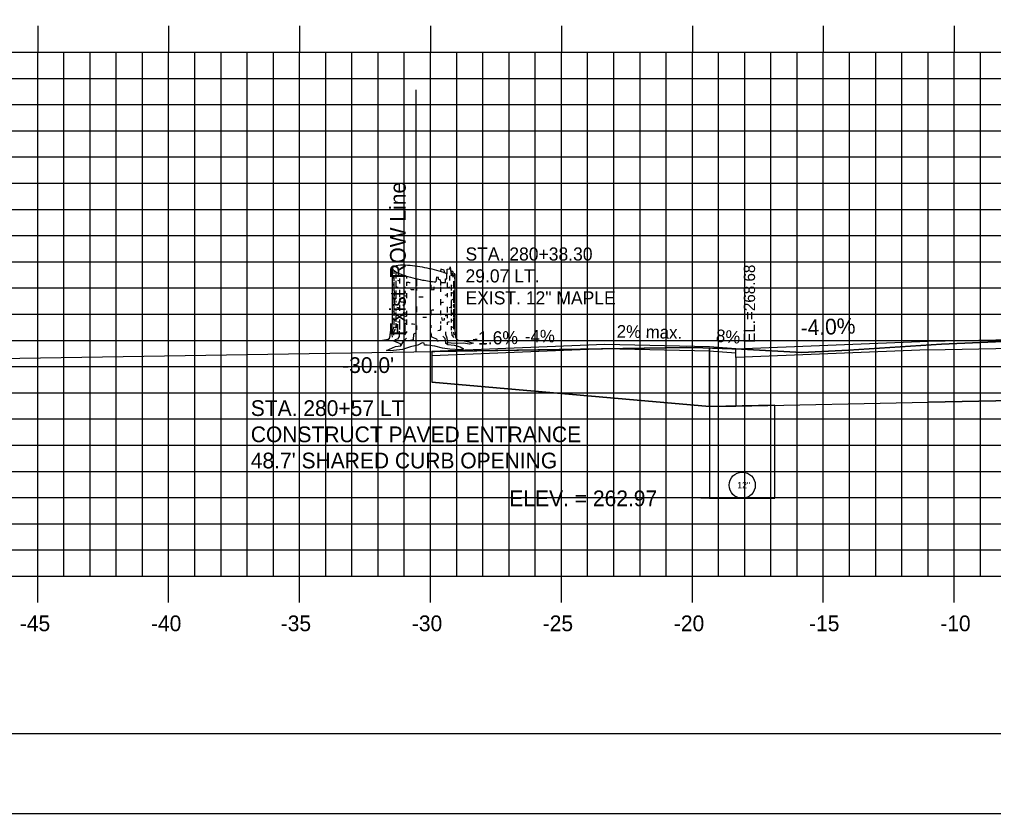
# Model space of a CAD drawing. Extents: x 855344 to 855514, y 366268 to 366378.
# Drawn here: x 855381.41 to 855418.61, y 366268.18 to 366298.48 of the extents above; entities that cross this region are included whole.
import ezdxf

# ---------------------------------------------------------------- set-up
doc = ezdxf.new("R2010")
doc.units = 0
for name, color, linetype in [('ANNOTATION', 7, 'Continuous'), ('BORDER', 7, 'Continuous'), ('D_Roadway_Drive_Gravel_LT', 7, 'Continuous'), ('D_Roadway_Drive_SubGrade', 7, 'Continuous'), ('D_Roadway_Edge_Shoulder', 7, 'Continuous'), ('D_Roadway_SubGrade', 7, 'Continuous'), ('D_Text_Monospaced', 7, 'Continuous'), ('D_Text_Standard', 7, 'Continuous'), ('E_ROW_Line', 7, 'Continuous'), ('H_V ANNOTATION', 7, 'Continuous'), ('JUNK COM EXC', 7, 'Continuous'), ('junk strct exc', 7, 'Continuous'), ('MAJOR', 7, 'Continuous'), ('MINOR', 7, 'Continuous'), ('PDRAIN', 7, 'Continuous'), ('PLOT BOUNDARY', 7, 'Continuous'), ('S_Roadway_Centerline', 7, 'Continuous'), ('S_Trees_Decid_Pay', 7, 'Continuous')]:
    doc.layers.add(name, color=color, linetype=linetype)

msp = doc.modelspace()

# ---------------------------------------------------------------- linework, layer by layer
at = {"layer": 'BORDER'}
msp.add_line((855352.11, 366271.236), (855512.11, 366271.236), dxfattribs=at)
at = {"layer": 'D_Roadway_Drive_Gravel_LT'}
for p, q in [((855403.764, 366286.075), (855397.155, 366285.81)), ((855407.764, 366285.995), (855403.764, 366286.075)), ((855408.764, 366285.915), (855407.764, 366285.995)), ((855403.771, 366285.908), (855397.155, 366285.643)), ((855407.761, 366285.828), (855403.761, 366285.908)), ((855408.764, 366285.747), (855407.751, 366285.828)), ((855408.764, 366285.581), (855408.764, 366285.915))]:
    msp.add_line(p, q, dxfattribs=at)
at = {"layer": 'D_Roadway_Drive_SubGrade'}
for p, q in [((855397.155, 366285.81), (855397.155, 366284.644)), ((855407.764, 366283.708), (855397.155, 366284.644)), ((855408.764, 366283.728), (855407.764, 366283.708))]:
    msp.add_line(p, q, dxfattribs=at)
at = {"layer": 'D_Roadway_Edge_Shoulder'}
msp.add_lwpolyline([(855408.764, 366285.915), (855416.11, 366286.208), (855427.11, 366286.428), (855438.11, 366286.208), (855442.107, 366286.048)], dxfattribs=at)
at = {"layer": 'D_Roadway_SubGrade'}
for points in [[(855416.11, 366283.875), (855416.11, 366285.875), (855427.11, 366286.095), (855438.11, 366285.875), (855438.11, 366283.875), (855427.11, 366284.095)], [(855416.11, 366285.875), (855408.764, 366285.581), (855408.764, 366283.728), (855416.11, 366283.875)]]:
    msp.add_lwpolyline(points, close=True, dxfattribs=at)
at = {"layer": 'D_Text_Standard'}
msp.add_lwpolyline([(855407.764, 366280.207), (855408.116, 366280.207), (855407.436, 366280.207)], dxfattribs=at)
at = {"layer": 'E_ROW_Line'}
msp.add_line((855396.563, 366285.801), (855396.563, 366295.801), dxfattribs=at)
at = {"layer": 'JUNK COM EXC'}
msp.add_lwpolyline([(855455.456, 366286.494), (855448.857, 366286.219), (855446.795, 366286.149), (855444.06, 366286.162), (855443.249, 366286.287), (855441.994, 366286.262), (855438.341, 366286.386), (855434.651, 366286.447), (855427.383, 366286.558), (855424.003, 366286.406), (855416.618, 366286.097), (855413.068, 366285.862), (855411.293, 366285.775), (855408.987, 366285.898), (855407.764, 366285.942), (855407.764, 366283.708), (855408.764, 366283.728), (855416.11, 366283.875), (855427.11, 366284.095), (855438.11, 366283.875), (855442.11, 366283.795), (855443.107, 366283.775), (855447.496, 366283.687), (855455.456, 366285.327)], close=True, dxfattribs=at)
msp.add_lwpolyline([(855407.764, 366285.942), (855407.512, 366285.951), (855406.881, 366285.969), (855397.155, 366285.81), (855397.155, 366284.644), (855407.764, 366283.708), (855407.764, 366285.942)], dxfattribs=at)
at = {"layer": 'junk strct exc'}
msp.add_lwpolyline([(855407.764, 366283.708), (855407.764, 366280.207), (855410.264, 366280.207), (855410.264, 366283.758)], close=True, dxfattribs=at)
at = {"layer": 'MAJOR'}
for p, q in [((855382.11, 366298.238), (855382.11, 366297.236)), ((855387.11, 366298.238), (855387.11, 366297.236)), ((855392.11, 366298.238), (855392.11, 366297.236)), ((855397.11, 366298.238), (855397.11, 366297.236)), ((855402.11, 366298.238), (855402.11, 366297.236)), ((855407.11, 366298.238), (855407.11, 366297.236)), ((855412.11, 366298.238), (855412.11, 366297.236)), ((855417.11, 366298.238), (855417.11, 366297.236)), ((855357.11, 366297.236), (855497.11, 366297.236)), ((855357.11, 366297.236), (855497.11, 366297.236)), ((855382.11, 366277.236), (855382.11, 366297.236)), ((855387.11, 366277.236), (855387.11, 366297.236)), ((855392.11, 366277.236), (855392.11, 366297.236)), ((855397.11, 366277.236), (855397.11, 366297.236)), ((855402.11, 366277.236), (855402.11, 366297.236)), ((855407.11, 366277.236), (855407.11, 366297.236)), ((855412.11, 366277.236), (855412.11, 366297.236)), ((855417.11, 366277.236), (855417.11, 366297.236)), ((855357.11, 366292.236), (855497.11, 366292.236)), ((855357.11, 366287.236), (855497.11, 366287.236)), ((855357.11, 366282.236), (855497.11, 366282.236)), ((855357.11, 366277.236), (855497.11, 366277.236)), ((855357.11, 366277.236), (855497.11, 366277.236)), ((855382.11, 366276.234), (855382.11, 366277.236)), ((855387.11, 366276.234), (855387.11, 366277.236)), ((855392.11, 366276.234), (855392.11, 366277.236)), ((855397.11, 366276.234), (855397.11, 366277.236)), ((855402.11, 366276.234), (855402.11, 366277.236)), ((855407.11, 366276.234), (855407.11, 366277.236)), ((855412.11, 366276.234), (855412.11, 366277.236)), ((855417.11, 366276.234), (855417.11, 366277.236))]:
    msp.add_line(p, q, dxfattribs=at)
at = {"layer": 'MINOR'}
for p, q in [((855383.11, 366277.236), (855383.11, 366297.236)), ((855384.11, 366277.236), (855384.11, 366297.236)), ((855385.11, 366277.236), (855385.11, 366297.236)), ((855386.11, 366277.236), (855386.11, 366297.236)), ((855388.11, 366277.236), (855388.11, 366297.236)), ((855389.11, 366277.236), (855389.11, 366297.236)), ((855390.11, 366277.236), (855390.11, 366297.236)), ((855391.11, 366277.236), (855391.11, 366297.236)), ((855393.11, 366277.236), (855393.11, 366297.236)), ((855394.11, 366277.236), (855394.11, 366297.236)), ((855395.11, 366277.236), (855395.11, 366297.236)), ((855396.11, 366277.236), (855396.11, 366297.236)), ((855398.11, 366277.236), (855398.11, 366297.236)), ((855399.11, 366277.236), (855399.11, 366297.236)), ((855400.11, 366277.236), (855400.11, 366297.236)), ((855401.11, 366277.236), (855401.11, 366297.236)), ((855403.11, 366277.236), (855403.11, 366297.236)), ((855404.11, 366277.236), (855404.11, 366297.236)), ((855405.11, 366277.236), (855405.11, 366297.236)), ((855406.11, 366277.236), (855406.11, 366297.236)), ((855408.11, 366277.236), (855408.11, 366297.236)), ((855409.11, 366277.236), (855409.11, 366297.236)), ((855410.11, 366277.236), (855410.11, 366297.236)), ((855411.11, 366277.236), (855411.11, 366297.236)), ((855413.11, 366277.236), (855413.11, 366297.236)), ((855414.11, 366277.236), (855414.11, 366297.236)), ((855415.11, 366277.236), (855415.11, 366297.236)), ((855416.11, 366277.236), (855416.11, 366297.236)), ((855418.11, 366277.236), (855418.11, 366297.236)), ((855357.11, 366296.236), (855497.11, 366296.236)), ((855357.11, 366295.236), (855497.11, 366295.236)), ((855357.11, 366294.236), (855497.11, 366294.236)), ((855357.11, 366293.236), (855497.11, 366293.236)), ((855357.11, 366291.236), (855497.11, 366291.236)), ((855357.11, 366290.236), (855497.11, 366290.236)), ((855357.11, 366289.236), (855497.11, 366289.236)), ((855357.11, 366288.236), (855497.11, 366288.236)), ((855357.11, 366286.236), (855497.11, 366286.236)), ((855357.11, 366285.236), (855497.11, 366285.236)), ((855357.11, 366284.236), (855497.11, 366284.236)), ((855357.11, 366283.236), (855497.11, 366283.236)), ((855357.11, 366281.236), (855497.11, 366281.236)), ((855357.11, 366280.236), (855497.11, 366280.236)), ((855357.11, 366279.236), (855497.11, 366279.236)), ((855357.11, 366278.236), (855497.11, 366278.236))]:
    msp.add_line(p, q, dxfattribs=at)
at = {"layer": 'PDRAIN'}
msp.add_lwpolyline([(855407.764, 366283.708), (855407.764, 366280.207), (855410.264, 366280.207), (855410.264, 366283.708)], dxfattribs=at)
msp.add_circle((855409.014, 366280.707), 0.5, dxfattribs=at)
at = {"layer": 'PLOT BOUNDARY'}
msp.add_lwpolyline([(855344.016, 366268.177), (855514.016, 366268.177), (855514.016, 366378.177), (855344.016, 366378.177)], close=True, dxfattribs=at)
at = {"layer": 'S_Roadway_Centerline'}
msp.add_lwpolyline([(855378.254, 366285.511), (855393.27, 366285.747), (855406.881, 366285.969), (855407.512, 366285.951), (855408.987, 366285.898), (855411.293, 366285.775), (855413.068, 366285.862), (855416.618, 366286.097), (855424.003, 366286.406), (855427.383, 366286.558), (855434.651, 366286.447), (855438.341, 366286.386), (855441.994, 366286.262), (855443.249, 366286.287), (855444.06, 366286.162), (855446.795, 366286.149), (855448.857, 366286.219), (855460.22, 366286.692)], dxfattribs=at)
at = {"layer": 'S_Trees_Decid_Pay'}
for p, q in [((855395.711, 366288.9), (855395.711, 366288.779)), ((855395.711, 366288.727), (855395.711, 366288.513)), ((855395.791, 366288.855), (855395.791, 366288.602)), ((855395.924, 366288.602), (855395.924, 366288.41)), ((855396.196, 366288.688), (855396.196, 366288.602)), ((855396.579, 366288.587), (855396.579, 366288.307)), ((855397.836, 366288.696), (855397.836, 366288.522)), ((855395.711, 366288.468), (855395.711, 366288.13)), ((855395.791, 366288.505), (855395.791, 366288.242)), ((855396.196, 366288.461), (855396.196, 366288.322)), ((855396.579, 366288.242), (855396.579, 366288.139)), ((855397.125, 366288.351), (855397.125, 366288.171)), ((855397.252, 366288.178), (855397.246, 366288.285)), ((855397.49, 366288.45), (855397.49, 366288.33)), ((855397.49, 366288.278), (855397.49, 366288.093)), ((855397.751, 366288.448), (855397.751, 366288.243)), ((855397.899, 366288.351), (855397.899, 366288.139)), ((855397.985, 366288.496), (855397.985, 366288.242)), ((855395.711, 366288.013), (855395.711, 366287.652)), ((855395.791, 366288.145), (855395.791, 366287.836)), ((855395.924, 366288.159), (855395.924, 366287.881)), ((855395.924, 366287.836), (855395.924, 366287.727)), ((855396.196, 366288.036), (855396.196, 366287.844)), ((855397.49, 366287.807), (855397.49, 366287.579)), ((855397.751, 366288.036), (855397.751, 366287.881)), ((855397.899, 366288.073), (855397.899, 366287.925)), ((855397.985, 366288.145), (855397.985, 366287.675)), ((855395.711, 366287.616), (855395.711, 366287.167)), ((855395.791, 366287.748), (855395.791, 366287.681)), ((855395.791, 366287.447), (855395.791, 366287.35)), ((855395.924, 366287.593), (855395.924, 366287.364)), ((855396.579, 366287.527), (855396.579, 366287.307)), ((855397.751, 366287.519), (855397.751, 366287.299)), ((855397.899, 366287.748), (855397.899, 366287.447)), ((855397.985, 366287.624), (855397.985, 366287.49)), ((855397.985, 366287.433), (855397.985, 366287.107)), ((855395.711, 366287.101), (855395.711, 366286.819)), ((855395.791, 366287.299), (855395.791, 366286.938)), ((855396.196, 366287.364), (855396.196, 366287.156)), ((855397.125, 366287.393), (855397.125, 366287.196)), ((855397.49, 366287.381), (855397.49, 366287.196)), ((855397.751, 366287.199), (855397.751, 366287.078)), ((855397.899, 366287.41), (855397.899, 366287.167)), ((855397.899, 366287.056), (855397.899, 366286.916)), ((855397.985, 366287.078), (855397.985, 366286.658)), ((855395.791, 366286.887), (855395.791, 366286.72)), ((855395.924, 366287.035), (855395.924, 366286.652)), ((855396.196, 366287.035), (855396.196, 366286.835)), ((855396.579, 366286.807), (855396.579, 366286.633)), ((855397.125, 366286.813), (855397.125, 366286.709)), ((855397.49, 366286.961), (855397.49, 366286.884)), ((855397.49, 366286.807), (855397.49, 366286.633)), ((855397.751, 366286.927), (855397.751, 366286.829)), ((855397.899, 366286.784), (855397.899, 366286.627)), ((855396.201, 366286.578), (855396.12, 366286.446)), ((855397.982, 366286.555), (855397.996, 366286.438))]:
    msp.add_line(p, q, dxfattribs=at)
for points in [[(855398.036, 366288.771), (855398.036, 366286.633), (855398.056, 366286.492), (855398.062, 366286.366), (855398.105, 366286.279), (855398.198, 366286.23), (855398.334, 366286.23), (855398.577, 366286.174), (855398.744, 366286.125), (855398.601, 366286.094), (855398.365, 366286.131), (855398.155, 366286.119), (855397.893, 366286.125), (855397.769, 366286.143), (855397.739, 366286.101), (855397.677, 366286.143), (855397.776, 366286.076), (855398.011, 366286.051), (855398.241, 366285.989), (855398.371, 366285.919), (855398.272, 366285.876), (855397.85, 366285.895), (855397.572, 366285.938), (855397.273, 366286.014), (855396.987, 366286.051), (855396.882, 366286.051), (855396.864, 366286.131), (855396.796, 366286.137), (855396.629, 366286.051), (855396.343, 366285.995), (855396.044, 366285.888), (855395.585, 366285.839), (855395.431, 366285.851), (855395.773, 366286.001), (855395.976, 366286.032), (855395.964, 366286.106), (855395.704, 366286.206), (855395.529, 366286.236), (855395.288, 366286.248), (855395.487, 366286.286), (855395.548, 366286.322), (855395.573, 366286.409), (855395.585, 366286.578), (855395.63, 366286.664), (855395.659, 366286.905), (855395.659, 366288.991)], [(855397.657, 366288.809), (855397.636, 366288.917), (855397.504, 366288.948), (855397.497, 366288.86)], [(855397.68, 366288.443), (855397.687, 366288.587), (855397.733, 366288.58), (855397.747, 366288.954), (855397.842, 366288.962), (855397.856, 366289.042), (855397.893, 366288.705), (855397.939, 366288.799), (855397.959, 366288.645), (855398.036, 366288.771), (855398.03, 366288.581)], [(855397.518, 366288.448), (855397.481, 366288.551), (855397.416, 366288.557), (855397.416, 366288.639), (855397.342, 366288.645), (855397.317, 366288.465)], [(855398.036, 366288.771), (855397.99, 366288.793), (855397.968, 366288.859), (855397.916, 366288.882), (855397.882, 366288.807)], [(855396.082, 366287.17), (855396.084, 366287.247), (855396.092, 366287.313)], [(855397.628, 366287.078), (855397.636, 366287.004), (855397.562, 366286.998), (855397.548, 366287.115)], [(855395.709, 366286.747), (855395.649, 366286.586), (855395.635, 366286.461), (855395.643, 366286.364)], [(855395.766, 366286.666), (855395.695, 366286.563), (855395.695, 366286.438)], [(855395.907, 366286.592), (855395.907, 366286.387), (855395.849, 366286.277), (855395.752, 366286.261)], [(855395.976, 366286.032), (855396.063, 366286.174), (855396.195, 366286.316)], [(855396.561, 366286.518), (855396.458, 366286.467), (855396.444, 366286.261), (855396.341, 366286.232)], [(855397.127, 366286.526), (855397.144, 366286.372), (855397.342, 366286.292), (855397.387, 366286.188)], [(855397.578, 366286.391), (855397.653, 366286.322), (855397.671, 366286.224), (855397.677, 366286.143)], [(855397.769, 366286.143), (855397.751, 366286.322), (855397.689, 366286.459), (855397.696, 366286.559)], [(855397.916, 366286.563), (855397.922, 366286.438), (855398.004, 366286.343)]]:
    msp.add_lwpolyline(points, dxfattribs=at)
for centre, radius, start, end in [((855395.705, 366288.991), 0.0467, 169.2221, 180.9043), ((855395.713, 366288.991), 0.0544, 180.9043, 191.7221), ((855395.705, 366288.991), 0.0467, 157.54, 169.2221), ((855395.723, 366288.993), 0.0645, 191.7221, 204.3989), ((855395.712, 366288.988), 0.0544, 146.7221, 157.54), ((855395.762, 366289.011), 0.107, 204.3989, 214.2221), ((855395.721, 366288.983), 0.0645, 134.0453, 146.7221), ((855395.809, 366289.043), 0.164, 214.2221, 228.4286), ((855395.75, 366288.952), 0.107, 124.2221, 134.0453), ((855395.782, 366288.905), 0.164, 110.0157, 124.2221), ((855396.018, 366289.279), 0.48, 228.4286, 236.7221), ((855395.89, 366288.609), 0.48, 101.7221, 110.0157), ((855396.057, 366287.806), 1.299, 86.3056, 101.7221), ((855395.746, 366282.99), 6.126, 79.2221, 86.3056), ((855395.746, 366282.99), 6.126, 72.1387, 79.2221), ((855395.713, 366288.665), 0.0554, 191.6815, 202.5), ((855395.722, 366288.668), 0.0657, 202.5, 215.1737), ((855395.758, 366288.693), 0.109, 215.1737, 225), ((855395.798, 366288.734), 0.166, 225, 238.33), ((855396.468, 366289.964), 1.299, 236.7221, 252.1387), ((855396.27, 366289.753), 1.292, 250.9084, 254.4349), ((855397.948, 366294.558), 6.126, 252.1387, 259.2221), ((855397.948, 366294.558), 6.126, 259.2221, 264.0853), ((855397.226, 366287.583), 1.299, 66.6931, 72.1387), ((855395.714, 366288.404), 0.0554, 191.6815, 202.5), ((855395.723, 366288.408), 0.0657, 202.5, 215.1737), ((855395.759, 366288.433), 0.109, 215.1737, 225), ((855395.799, 366288.473), 0.166, 225, 239.1924), ((855395.962, 366288.746), 0.484, 239.1924, 242.5838), ((855396.271, 366289.492), 1.292, 247.5, 251.9171), ((855396.846, 366294.341), 5.916, 263.6913, 265.0485), ((855396.847, 366294.08), 5.916, 265.1076, 266.4618), ((855396.847, 366294.08), 5.916, 272.6957, 273.9224), ((855397.948, 366294.558), 6.126, 265.9754, 266.3056), ((855397.637, 366289.742), 1.299, 266.3056, 271.8711), ((855397.423, 366289.492), 1.292, 284.7144, 289.3881), ((855397.895, 366288.473), 0.166, 300.8076, 315), ((855397.935, 366288.433), 0.109, 315, 324.8263), ((855397.971, 366288.408), 0.0657, 324.8263, 337.5), ((855397.98, 366288.404), 0.0554, 337.5, 348.3185), ((855397.988, 366288.402), 0.0476, 348.3185, 0), ((855395.714, 366287.883), 0.0554, 191.6815, 202.5), ((855395.723, 366287.887), 0.0657, 202.5, 215.1737), ((855395.759, 366287.912), 0.109, 215.1737, 225), ((855395.799, 366287.952), 0.166, 225, 239.1924), ((855395.799, 366288.21), 0.166, 238.3999, 239.1924), ((855395.962, 366288.483), 0.484, 239.1924, 247.5), ((855395.962, 366288.225), 0.484, 239.1924, 245.3628), ((855396.271, 366289.229), 1.292, 247.5, 248.1929), ((855396.271, 366289.229), 1.292, 261.6338, 262.8454), ((855396.847, 366293.817), 5.916, 262.8454, 263.6816), ((855396.847, 366293.817), 5.916, 268.2292, 269.8838), ((855397.423, 366289.229), 1.292, 280.7368, 284.7144), ((855397.423, 366289.229), 1.292, 291.6463, 292.5), ((855397.732, 366288.483), 0.484, 292.5, 300.8076), ((855397.732, 366288.225), 0.484, 294.2275, 300.8076), ((855397.895, 366288.21), 0.166, 300.8076, 302.9622), ((855397.895, 366287.952), 0.166, 300.8076, 315), ((855397.935, 366287.912), 0.109, 315, 324.8263), ((855397.971, 366287.887), 0.0657, 324.8263, 337.5), ((855397.98, 366287.883), 0.0554, 337.5, 348.3185), ((855397.988, 366287.881), 0.0476, 348.3185, 0), ((855395.714, 366287.625), 0.0554, 191.6815, 202.5), ((855395.723, 366287.629), 0.0657, 202.5, 215.1737), ((855395.759, 366287.654), 0.109, 215.1737, 225), ((855395.799, 366287.695), 0.166, 225, 237.9306), ((855396.271, 366288.714), 1.292, 249.8999, 254.3895), ((855396.271, 366288.972), 1.292, 254.3895, 260.7435), ((855396.847, 366293.559), 5.916, 276.2405, 277.1546), ((855397.423, 366288.972), 1.292, 277.1546, 278.1274), ((855397.423, 366288.714), 1.292, 288.201, 292.5), ((855397.423, 366288.972), 1.292, 291.5158, 292.5), ((855397.895, 366287.695), 0.166, 300.8076, 315), ((855397.935, 366287.654), 0.109, 315, 324.8263), ((855397.971, 366287.629), 0.0657, 324.8263, 337.5), ((855397.98, 366287.625), 0.0554, 337.5, 348.3185), ((855397.988, 366287.624), 0.0476, 348.3185, 0), ((855395.714, 366287.36), 0.0554, 191.6815, 202.5), ((855395.714, 366287.088), 0.0554, 191.6815, 202.5), ((855395.723, 366287.092), 0.0657, 202.5, 215.1737), ((855395.759, 366287.117), 0.109, 215.1737, 225), ((855395.799, 366287.429), 0.166, 237.9306, 239.1924), ((855395.962, 366287.702), 0.484, 239.1924, 247.5), ((855396.271, 366288.449), 1.292, 261.6205, 262.8454), ((855396.847, 366293.037), 5.916, 262.8454, 263.6816), ((855396.847, 366293.037), 5.916, 269.7243, 270), ((855396.847, 366293.037), 5.916, 270, 271.0793), ((855396.847, 366293.302), 5.916, 272.6957, 273.7279), ((855397.423, 366288.449), 1.292, 280.7537, 284.7144), ((855397.423, 366288.449), 1.292, 291.6463, 292.5), ((855397.732, 366287.702), 0.484, 292.5, 300.8076), ((855397.895, 366287.429), 0.166, 300.8076, 315), ((855397.935, 366287.389), 0.109, 315, 324.8263), ((855397.971, 366287.364), 0.0657, 324.8263, 337.5), ((855397.98, 366287.36), 0.0554, 337.5, 348.3185), ((855397.988, 366287.358), 0.0476, 348.3185, 0), ((855395.799, 366287.158), 0.166, 225, 237.9306), ((855395.962, 366287.173), 0.484, 243.4501, 247.5), ((855396.262, 366287.923), 1.292, 247.9396, 248.6304), ((855396.271, 366288.177), 1.292, 250.8466, 254.3895), ((855396.271, 366288.177), 1.292, 261.6338, 262.8454), ((855396.847, 366292.765), 5.916, 262.8454, 263.6816), ((855396.847, 366292.765), 5.916, 265.539, 266.7363), ((855397.423, 366288.177), 1.292, 284.7144, 288.6336), ((855397.423, 366287.919), 1.292, 291.6463, 292.5), ((855397.732, 366287.431), 0.484, 292.5, 297.266), ((855397.732, 366287.173), 0.484, 292.5, 300.8076), ((855397.895, 366286.9), 0.166, 300.8076, 315), ((855397.935, 366286.86), 0.109, 315, 324.8263), ((855397.971, 366286.835), 0.0657, 324.8263, 337.5), ((855397.98, 366286.831), 0.0554, 337.5, 348.3185), ((855397.988, 366286.829), 0.0476, 348.3185, 0), ((855396.847, 366292.507), 5.916, 275.2344, 276.2169)]:
    msp.add_arc(centre, radius, start, end, dxfattribs=at)

# ---------------------------------------------------------------- texts
at = {"layer": 'ANNOTATION'}
msp.add_text('-4.0%', height=0.6, rotation=2.2906, dxfattribs=at).set_placement((855411.253, 366286.415))
for s, p in [('STA. 280+57 LT', (855390.247, 366283.35)), ('CONSTRUCT PAVED ENTRANCE', (855390.247, 366282.35)), ("48.7' SHARED CURB OPENING", (855390.247, 366281.35))]:
    msp.add_text(s, height=0.6, dxfattribs=at).set_placement(p)
at = {"layer": 'D_Roadway_Drive_Gravel_LT'}
for s, rotation, p in [('2% max.', 358.8078, (855404.218, 366286.345)), ('8%', 355.4261, (855407.995, 366286.182))]:
    msp.add_text(s, height=0.48, rotation=rotation, dxfattribs=at).set_placement(p)
msp.add_text(' -4%', height=0.48, dxfattribs=at).set_placement((855400.538, 366286.158))
at = {"layer": 'D_Text_Monospaced'}
for s, height, p in [('STA. 280+38.30', 0.49998, (855398.447, 366289.282)), ('29.07 LT.', 0.5, (855398.447, 366288.448)), ('EXIST. 12" MAPLE', 0.49998, (855398.447, 366287.608))]:
    msp.add_text(s, height=height, dxfattribs=at).set_placement(p)
msp.add_text('-1.6%', height=0.5, rotation=0.6898, dxfattribs=at).set_placement((855398.705, 366286.072))
at = {"layer": 'D_Text_Standard'}
msp.add_text(' EL.=268.68', height=0.4335, rotation=90, dxfattribs=at).set_placement((855409.504, 366285.982))
for s, p in [("-30.0'", (855393.736, 366284.991)), ('ELEV. = 262.97', (855400.122, 366279.907))]:
    msp.add_text(s, height=0.6, dxfattribs=at).set_placement(p)
at = {"layer": 'E_ROW_Line'}
msp.add_text('Exist. ROW Line', height=0.6, rotation=90, dxfattribs=at).set_placement((855396.163, 366286.401))
at = {"layer": 'H_V ANNOTATION'}
for s, p in [('-45', (855381.427, 366275.136)), ('-40', (855386.435, 366275.136)), ('-35', (855391.39, 366275.136)), ('-30', (855396.398, 366275.136)), ('-25', (855401.395, 366275.136)), ('-20', (855406.403, 366275.136)), ('-15', (855411.566, 366275.136)), ('-10', (855416.575, 366275.136))]:
    msp.add_text(s, height=0.6, dxfattribs=at).set_placement(p)
at = {"layer": 'PDRAIN'}
msp.add_text('12"', height=0.25, dxfattribs=at).set_placement((855408.823, 366280.583))

doc.saveas('drawing.dxf')
